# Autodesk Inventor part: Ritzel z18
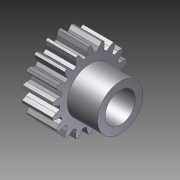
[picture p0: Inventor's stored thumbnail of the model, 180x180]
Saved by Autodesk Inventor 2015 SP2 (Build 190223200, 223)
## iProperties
Created: 2015-08
Part Number: Ritzel z18
Material: Edelstahl
Document SubType Name: Modeling
Designer: rYan
Mass: 2.45838 g
Surface Area: 4.73997 cm^2
Volume: 0.307298 cm^3
Density: 8 g/cm^3
Appearance: Halbpoliert
Title: c:/PPEXPORT/antriebselemente_und_normteile/stirnzahnraeder/stirnzahnraeder_stahl/modul_05_und_07/artikel_nr___21101800.stp
Creation Date: 2007-11-07
Author: rYan
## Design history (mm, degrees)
node "211018001"
sketch "Skizze1"
  geometry: 2 further points
  constraints: 1 coincident
hole "Bohrung1" sketch "Skizze1" at (0, 0) diameter "d0" = 4; stored, may be unused: countersink angle "d4" = 90 deg, drill point angle "d6" = 118 deg; dims "d1" = 6, "d2" = 4, "d3" = 2, "d5" = 8
node "1"
node "Basis1"
